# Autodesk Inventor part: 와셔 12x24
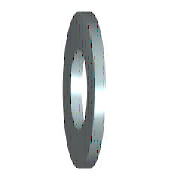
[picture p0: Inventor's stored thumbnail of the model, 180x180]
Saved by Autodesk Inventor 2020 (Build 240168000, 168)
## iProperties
IsCustomPart: 1
Created: 2012-02
Part Number: 와셔 12x24
Material: 스테인리스강
Description: 평면 와셔
Document SubType Name: Modeling
Standard: KS B 1326
Designer: mduedu
Standards Organization: KS
Language: ko-KR
Size Designation: 12x24
Categories: <MemberInstance><Categories><Category DisplayName="조임쇠" InternalName="e4da775c-781d-43d5-af7c-5136215cf5a6" Mnemonic="FSTN"><Category DisplayName="와셔" InternalN
Density: 1 g/cm^3
Appearance: 파란색 - 벽 페인트 - 광택
Author: mduedu
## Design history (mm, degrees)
sketch "스케치"
  geometry: C1 r 12 at (0, 0); C2 r 6.5 at (0, 0); 1 further point
  constraints: 2 centre point, 2 coincident
  dimensions: "d0" = 13 diameter of C2 (= SD1); "d1" = 24 diameter of C1 (= SD2)
extrude "본체" new body sketch "스케치" distance "d2" = 3 (= SD); taper "d3" = 0 deg
workaxis "Work Axis1"
workplane "Work Plane1"
body "Solid1"
other parameters: "SD1" = 13 [user parameter; used in 1 equation term], "SD2" = 24 [user parameter; used in 1 equation term], "SD" = 3 [user parameter; used in 1 equation term], "d4" = 0, "d5" = 0, "d6" = 0, "d7" = 0, "NND" = 12 [user parameter]
